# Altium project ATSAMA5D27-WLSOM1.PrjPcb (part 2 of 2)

## Sheet 04 - WiFi-BLE-Flash.SchDoc
size B; CompanyName: Microchip Technology Inc.; Organization: Microchip Technology; Address1: 2355 West Chandler Blvd.; Address2: Chandler, AZ  85224; Address4: USA; SheetNumber: 5; SheetTotal: 6; SheetTitle: WiFi/BLE/FLASH
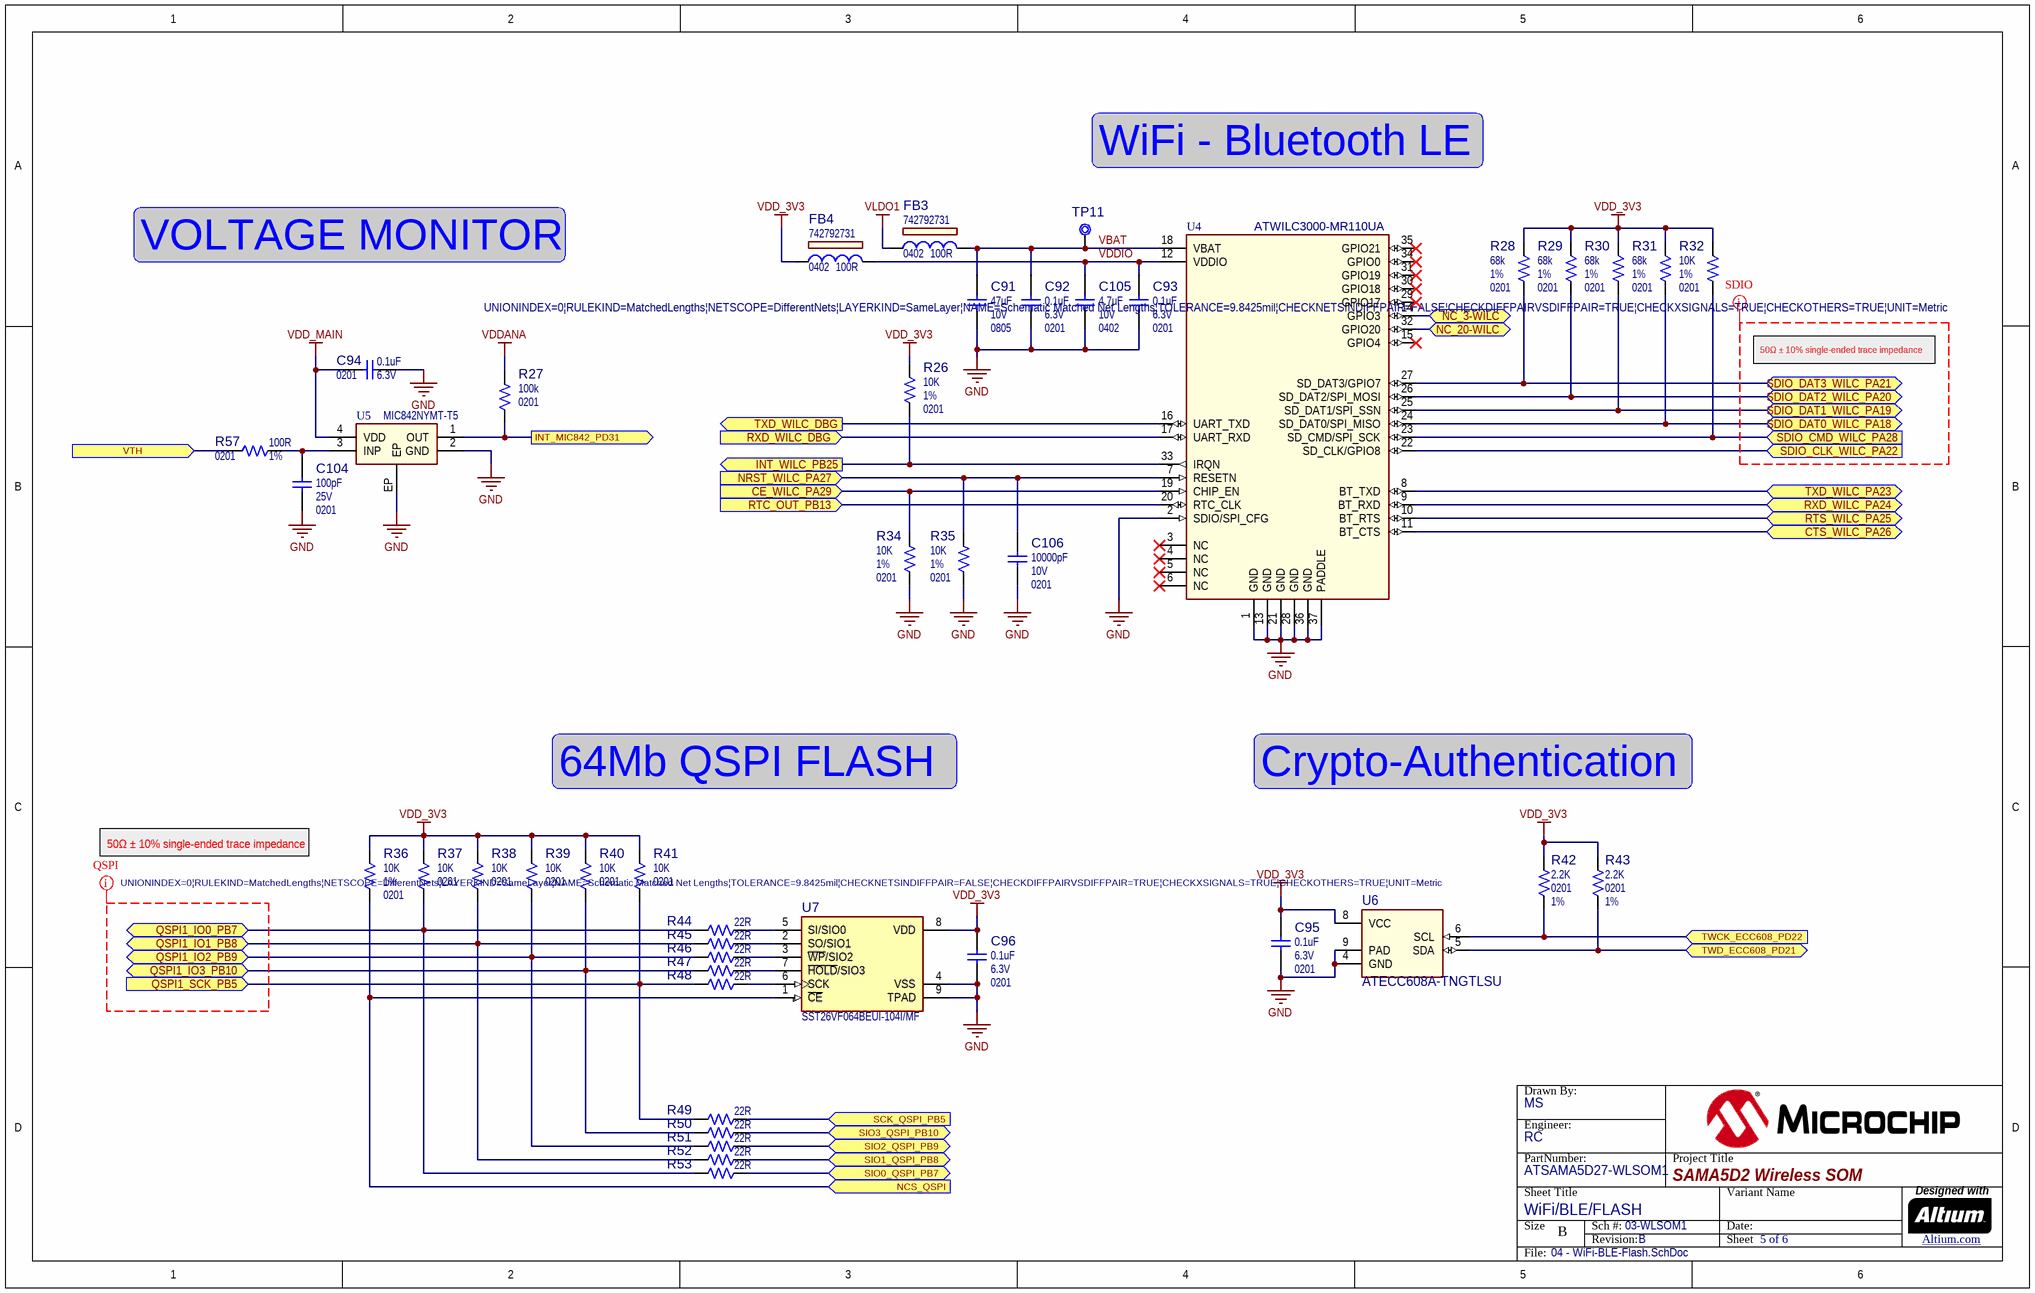
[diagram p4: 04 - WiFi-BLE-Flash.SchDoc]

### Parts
(Parts that share a designator on the sheet are numbered #1, #2 ... from top to bottom, then left to right.)
?#5  (no value)  (graphical)
C91  value 47uF  Voltage: 10V  Package: 0805  [RES_C_0805]  (hidden comment: Capacitor NP)
C92  value 0.1uF  Voltage: 6.3V  Package: 0201  [CAP_C_0201]  (hidden comment: Capacitor NP)
C93  value 0.1uF  Voltage: 6.3V  Package: 0201  [CAP_C_0201]  (hidden comment: Capacitor NP)
C94  value 0.1uF  Voltage: 6.3V  Package: 0201  [CAP_C_0201]  (hidden comment: Capacitor NP)
C95  value 0.1uF  Voltage: 6.3V  Package: 0201  [CAP_C_0201]  (hidden comment: Capacitor NP)
C96  value 0.1uF  Voltage: 6.3V  Package: 0201  [CAP_C_0201]  (hidden comment: Capacitor NP)
C104  value 100pF  Voltage: 25V  Package: 0201  [CAP_C_0201]  (hidden comment: Capacitor NP)
C105  value 4.7uF  Voltage: 10V  Package: 0402  [CAP_C_0402]  (hidden comment: Capacitor NP)
C106  value 10000pF  Voltage: 10V  Package: 0201  [CAP_C_0201]  (hidden comment: Capacitor NP)
FB3  value 100R  Package: 0402  Manufacturer Part Number 1: 742792731  [IND_C_0402]  (hidden comment: Ferrite Bead)
FB4  value 100R  Package: 0402  Manufacturer Part Number 1: 742792731  [IND_C_0402]  (hidden comment: Ferrite Bead)
R26  value 10K  Package: 0201  Tolerance: 1%  [RES_C_0201]  (hidden comment: Resistor)
R27  value 100k  Package: 0201  [RES_C_0201]  (hidden comment: Resistor)
R28  value 68k  Package: 0201  Tolerance: 1%  [RES_C_0201]  (hidden comment: Resistor)
R29  value 68k  Package: 0201  Tolerance: 1%  [RES_C_0201]  (hidden comment: Resistor)
R30  value 68k  Package: 0201  Tolerance: 1%  [RES_C_0201]  (hidden comment: Resistor)
R31  value 68k  Package: 0201  Tolerance: 1%  [RES_C_0201]  (hidden comment: Resistor)
R32  value 10K  Package: 0201  Tolerance: 1%  [RES_C_0201]  (hidden comment: Resistor)
R34  value 10K  Package: 0201  Tolerance: 1%  [RES_C_0201]  (hidden comment: Resistor)
R35  value 10K  Package: 0201  Tolerance: 1%  [RES_C_0201]  (hidden comment: Resistor)
R36  value 10K  Package: 0201  Tolerance: 1%  [RES_C_0201]  (hidden comment: Resistor)
R37  value 10K  Package: 0201  [RES_C_0201]  (hidden comment: Resistor)
R38  value 10K  Package: 0201  [RES_C_0201]  (hidden comment: Resistor)
R39  value 10K  Package: 0201  [RES_C_0201]  (hidden comment: Resistor)
R40  value 10K  Package: 0201  [RES_C_0201]  (hidden comment: Resistor)
R41  value 10K  Package: 0201  [RES_C_0201]  (hidden comment: Resistor)
R42  value 2.2K  Package: 0201  Tolerance: 1%  [RES_C_0201]  (hidden comment: Resistor)
R43  value 2.2K  Package: 0201  Tolerance: 1%  [RES_C_0201]  (hidden comment: Resistor)
R44  value 22R  [RES_C_0201]  (hidden comment: Resistor)
R45  value 22R  [RES_C_0201]  (hidden comment: Resistor)
R46  value 22R  [RES_C_0201]  (hidden comment: Resistor)
R47  value 22R  [RES_C_0201]  (hidden comment: Resistor)
R48  value 22R  [RES_C_0201]  (hidden comment: Resistor)
R49  value 22R  [RES_C_0201]  (hidden comment: Resistor)
R50  value 22R  [RES_C_0201]  (hidden comment: Resistor)
R51  value 22R  [RES_C_0201]  (hidden comment: Resistor)
R52  value 22R  [RES_C_0201]  (hidden comment: Resistor)
R53  value 22R  [RES_C_0201]  (hidden comment: Resistor)
R57  value 100R  Package: 0201  Tolerance: 1%  [RES_C_0201]  (hidden comment: Resistor)
TP11  Test Point No BOM  [TP_1mm_SMD]  (value not drawn)  (no BOM)
U4  value ATWILC3000-MR110UA  [MODULE ATWILC3000-MR110CA]  (hidden comment: MODULE ATWILC3000-MR110CA)
U5  Manufacturer Part Number 1: MIC842NYMT-T5  [TDFN-4_1.6x1.2]  (hidden comment: MIC842 TDFN-4)
U6  value ATECC608A-TNGTLSU  [UDFN-8_2X3_EP1.5X1.3]  (hidden comment: ATECC608A-TNGTLSU UDFN-8)
U7  value SST26VF064BEUI-104I/MF  [WSON-8_6x5_EP3.4X4.0]  (hidden comment: SST26VF064B-104IMF)

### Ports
CE_WILC_PA29 (in), CTS_WILC_PA26 (bidir), INT_MIC842_PD31 (out), INT_WILC_PB25 (out), NC_3-WILC (bidir), NC_20-WILC (bidir), NCS_QSPI (in), NRST_WILC_PA27 (in), QSPI1_IO0_PB7 (bidir), QSPI1_IO1_PB8 (bidir), QSPI1_IO2_PB9 (bidir), QSPI1_IO3_PB10 (bidir), QSPI1_SCK_PB5 (in), RTC_OUT_PB13 (in), RTS_WILC_PA25 (bidir), RXD_WILC_DBG (in), RXD_WILC_PA24 (bidir), SCK_QSPI_PB5 (in), SDIO_CLK_WILC_PA22 (in), SDIO_CMD_WILC_PA28 (in), SDIO_DAT0_WILC_PA18 (bidir), SDIO_DAT1_WILC_PA19 (bidir), SDIO_DAT2_WILC_PA20 (bidir), SDIO_DAT3_WILC_PA21 (bidir), SIO0_QSPI_PB7 (bidir), SIO1_QSPI_PB8 (bidir), SIO2_QSPI_PB9 (bidir), SIO3_QSPI_PB10 (bidir), TWCK_ECC608_PD22 (in), TWD_ECC608_PD21 (bidir), TXD_WILC_DBG (out), TXD_WILC_PA23 (bidir), VTH (in)

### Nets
GND: C91.1 C92.1 C93.1 C94.1 C95.1 C96.1 C104.1 C105.1 C106.1 R34.1 R35.1 U4.1(GND) U4.2(SDIO/SPI_CFG) U4.13(GND) U4.21(GND) U4.28(GND) U4.36(GND) U4.37(PADDLE) U5.2(GND) U5.EP U6.4(GND) U6.9(PAD) U7.4(VSS) U7.9(TPAD)
VDD_3V3: C95.2 C96.2 FB4.1 R26.2 R28.2 R29.2 R30.2 R31.2 R32.2 R36.2 R37.2 R38.2 R39.2 R40.2 R41.2 R42.2 R43.2 U6.8(VCC) U7.8(VDD)
VDD_MAIN: C94.2 U5.4(VDD)
VDDANA: R27.2
VLDO1: FB3.1
CE_WILC_PA29: R34.2 U4.19(CHIP_EN) ; port CE_WILC_PA29
CTS_WILC_PA26: U4.11(BT_CTS) ; port CTS_WILC_PA26
INT_MIC842_PD31: R27.1 U5.1(OUT) ; port INT_MIC842_PD31
INT_WILC_PB25: R26.1 U4.33(IRQN) ; port INT_WILC_PB25
NC_3-WILC: U4.14(GPIO3) ; port NC_3-WILC
NC_20-WILC: U4.32(GPIO20) ; port NC_20-WILC
NCS_QSPI: R36.1 U7.1(~{CE}) ; port NCS_QSPI
NRST_WILC_PA27: C106.2 R35.2 U4.7(RESETN) ; port NRST_WILC_PA27
QSPI1_IO0_PB7: R37.1 R44.1 R53.1 ; port QSPI1_IO0_PB7
QSPI1_IO1_PB8: R38.1 R45.1 R52.1 ; port QSPI1_IO1_PB8
QSPI1_IO2_PB9: R39.1 R46.1 R51.1 ; port QSPI1_IO2_PB9
QSPI1_IO3_PB10: R40.1 R47.1 R50.1 ; port QSPI1_IO3_PB10
QSPI1_SCK_PB5: R41.1 R48.1 R49.1 ; port QSPI1_SCK_PB5
RTC_OUT_PB13: U4.20(RTC_CLK) ; port RTC_OUT_PB13
RTS_WILC_PA25: U4.10(BT_RTS) ; port RTS_WILC_PA25
RXD_WILC_DBG: U4.17(UART_RXD) ; port RXD_WILC_DBG
RXD_WILC_PA24: U4.9(BT_RXD) ; port RXD_WILC_PA24
SCK_QSPI_PB5: R49.2 ; port SCK_QSPI_PB5
SDIO_CLK_WILC_PA22: U4.22(SD_CLK/GPIO8) ; port SDIO_CLK_WILC_PA22
SDIO_CMD_WILC_PA28: R32.1 U4.23(SD_CMD/SPI_SCK) ; port SDIO_CMD_WILC_PA28
SDIO_DAT0_WILC_PA18: R31.1 U4.24(SD_DAT0/SPI_MISO) ; port SDIO_DAT0_WILC_PA18
SDIO_DAT1_WILC_PA19: R30.1 U4.25(SD_DAT1/SPI_SSN) ; port SDIO_DAT1_WILC_PA19
SDIO_DAT2_WILC_PA20: R29.1 U4.26(SD_DAT2/SPI_MOSI) ; port SDIO_DAT2_WILC_PA20
SDIO_DAT3_WILC_PA21: R28.1 U4.27(SD_DAT3/GPIO7) ; port SDIO_DAT3_WILC_PA21
SIO0_QSPI_PB7: R53.2 ; port SIO0_QSPI_PB7
SIO1_QSPI_PB8: R52.2 ; port SIO1_QSPI_PB8
SIO2_QSPI_PB9: R51.2 ; port SIO2_QSPI_PB9
SIO3_QSPI_PB10: R50.2 ; port SIO3_QSPI_PB10
TWCK_ECC608_PD22: R42.1 U6.6(SCL) ; port TWCK_ECC608_PD22
TWD_ECC608_PD21: R43.1 U6.5(SDA) ; port TWD_ECC608_PD21
TXD_WILC_DBG: U4.16(UART_TXD) ; port TXD_WILC_DBG
TXD_WILC_PA23: U4.8(BT_TXD) ; port TXD_WILC_PA23
VBAT: C91.2 C92.2 FB3.2 TP11.1 U4.18(VBAT)
VDDIO: C93.2 C105.2 FB4.2 U4.12(VDDIO)
VTH: R57.1 ; port VTH
NetC104_2: C104.2 R57.2 U5.3(INP)
NetR44_2: R44.2 U7.5(SI/SIO0)
NetR45_2: R45.2 U7.2(SO/SIO1)
NetR46_2: R46.2 U7.3(~{WP}/SIO2)
NetR47_2: R47.2 U7.7(~{HOLD}/SIO3)
NetR48_2: R48.2 U7.6(SCK)

Not connected (* = marked no-connect by the designer): U4 3(NC)* 4(NC)* 5(NC)* 6(NC)* 15(GPIO4)* 29(GPIO17)* 30(GPIO18)* 31(GPIO19)* 34(GPIO0)* 35(GPIO21)*

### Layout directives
net class QSPI; rule Matched Net Lengths [Tolerance = 0.25mm]: (no net found under the mark)
net class SDIO; rule Matched Net Lengths [Tolerance = 0.25mm]: (no net found under the mark)

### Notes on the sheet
- WiFi - Bluetooth LE
- VOLTAGE MONITOR
- 50Ω ± 10% single-ended trace impedance
- 64Mb QSPI FLASH
- Crypto-Authentication

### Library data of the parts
?#5 = Title Block B
C91 = CAP2000: Capacitor; Manufacturer 1: Murata Electronics North America; Manufacturer Part Number 1: GRM21BR61A476ME15L; Description_: CAP CER 47uF 10V 20% X5R 0805; Dev Tools Status: Design; Tolerance: 20%; Temperature Coeffcient: X5R; ESR: 0.3R; Type: Ceramic; Owner: Dragos Danaila; Populated: YES
C92-C96 = CAP2003: Capacitor; Manufacturer 1: KEMET; Manufacturer Part Number 1: C0201C104K9PACTU; Description_: CAP CER 0.1uF 6.3V 10% X5R 0201; Dev Tools Status: Design; Tolerance: 10%; Temperature Coeffcient: X5R; Owner: Dragos Danaila; Populated: YES; ESR: 0.005R; Type: Ceramic
C104 = CAP1450: Capacitor; Manufacturer 1: Murata Electronics North America; Manufacturer Part Number 1: GRM0335C1E101JA01D; Description_: CAP CER 100pF 25V 5% NP0 SMD 0201; Dev Tools Status: Design; Tolerance: 5%; Temperature Coeffcient: NP0; Type: Ceramic; Owner: Gabor Bihari; Populated: YES
C105 = CAP1684: Capacitor; Manufacturer 1: TDK Corporation; Manufacturer Part Number 1: C1005X5R1A475K050BC; Description_: CAP CER 4.7uF 10V 10% X5R SMD 0402; Dev Tools Status: Production; Tolerance: 10%; Temperature Coeffcient: X5R; Type: Ceramic; Owner: Jesus Aviles; Populated: YES
C106 = CAP1201: Capacitor; Manufacturer 1: Murata; Manufacturer Part Number 1: GRM033R61A103KA01D; Description_: CAP CER 10000pF 10V 10% X5R SMD 0201; Dev Tools Status: Production; Tolerance: 10%; Temperature Coeffcient: X5R; Type: Ceramic; Owner: Tad Ahlvers; Populated: YES
FB3 FB4 = IND1642: Manufacturer 1: Wurth Electronics; Description_: FERRITE 100R@100MHz 1.2A SMD 0402; Dev Tools Status: Design; Owner: Dragos Danaila; DCR: 0.09R; RMS Current: 1.2A; Test Frequency: 100MHz; Populated: YES
R26 R32 R34-R36 = RSMT1252: Manufacturer 1: Yageo; Manufacturer Part Number 1: RC0201FR-0710KL; Description_: RES TKF 10K 1% 1/20W SMD 0201; Dev Tools Status: Design; Voltage: 25V; Temperature Coeffcient: 200pm/C; Power: 1/20W; Owner: Dragos Danaila; Populated: YES
R27 = RES1582: Manufacturer 1: Panasonic Electronic Components; Manufacturer Part Number 1: ERJ-1GEF1003C; Tolerance: 1%; Description_: RES TKF 100k 1% 1/20W SMD 0201; Dev Tools Status: Design; Voltage: 15V; Temperature Coeffcient: 200ppm/C; Power: 1/20W; Owner: Gabor Bihari; Populated: YES
R28-R31 = RES2264: Manufacturer 1: Yageo; Manufacturer Part Number 1: RC0201FR-0768KL; Description_: RES TKF 68K 1/20W SMD 0201; Dev Tools Status: Design; Voltage: 25V; Temperature Coeffcient: 200ppm/C; Power: 1/20W; Owner: Dragos Danaila; Populated: YES
R37-R41 = RSMT1252: Manufacturer 1: Yageo; Manufacturer Part Number 1: RC0201FR-0710KL; Tolerance: 1%; Description_: RES TKF 10K 1% 1/20W SMD 0201; Dev Tools Status: Design; Voltage: 25V; Temperature Coeffcient: 200pm/C; Power: 1/20W; Owner: Dragos Danaila; Populated: DNP
R42 R43 = RSMT1251: Manufacturer 1: Vishay Dale; Manufacturer Part Number 1: CRCW02012K20FKED; Description_: RES TKF 2.2K 1/20W SMD 0201; Dev Tools Status: Design; Voltage: 25V; Temperature Coeffcient: 100ppm/C; Current: 0.5A; Power: 1/20W; Owner: Dragos Danaila; Populated: YES
R44-R53 = RES1473: Manufacturer 1: Panasonic Electronic Components; Manufacturer Part Number 1: ERJ-1GEF22R0C; Tolerance: 1%; Description_: RES TKF 22R 1% 1/20W SMD 0201; Dev Tools Status: Design; Voltage: 25V; Power: 1/20W; Owner: Mike Ragsdale; Populated: YES
R57 = RES2175: Manufacturer 1: Yageo; Manufacturer Part Number 1: RC0201FR-07100RL; Description_: RES TKF 100R 1% 1/20W SMD 0201; Dev Tools Status: Design; Voltage: 25V; Temperature Coeffcient: 200ppm/C; Current: 0.5A; Power: 1/20W; Owner: Dragos Danaila; Populated: YES
TP11 = CON1759: Test Point; Value: TP PAD PCB 1mm; Description_: CON TP PAD PCB 1mm SMD; Dev Tools Status: Design; Owner: Cristian Papuc; Populated: YES
U4 = MIC8126: Manufacturer 1: Microchip Technology; Description_: MCHP RF WI-FI 802.11b/g/n ATWILC3000-MR110UA; MAPS Description: SmartConnect WILC3000-MR110UA Module; Dev Tools Status: Design; Owner: Ilie Galan; tblDeviceFamilyID: 11256; FrequencyRange: 2.412-2.472 MHz; MaxSpeedMHz: 0; PowerRX: 84mA (802.11n MCS7); PowerTX: 253mA (802.11n MCS7); Sleep: 1.25uA; Populated: YES
U5 = MIC8024: Manufacturer 1: Microchip Technology; Description_: MCHP ANALOG COMPARATOR 1-CH MIC842NYMT-T5 4-TDFN; MAPS Description: 1.5uA Undervoltage Comparator w/ 1.25% 1.24V Reference, 20mV Hysteresis, Active-; Dev Tools Status: Design; Owner: Dragos Danaila; MPC: 27809THGAE06; LeadContent: Pb-FREE; PackingMedia: T/R; Stage: REL; LeadCount: 4; PackageWidth: 1.2x1.6x0.6mm; ForceMinOrderQtyMult: True; MinOrderQty: 500; TempRange: -40C to +85C; tblDeviceFamilyID: 10172; VDDmax: 0; Channels: 1; TypicalPropDelay: 12000; RailIn: False; Populated: YES
U6 = MIC8843: Manufacturer 1: Microchip Technology Inc; Manufacturer Part Number 1: ATECC608A-TNGTLSU-C; Description_: MCHP INTERFACE CRYPTOAUTH I2C ATECC608A-TNGTLS UDFN8; Dev Tools Status: Design; Owner: Dragos Danaila; Populated: YES
U7 = MIC8649: SQI Serial Flash; Manufacturer 1: Microchip Technology; Description_: MCHP SERIAL FLASH SST26VF064BEUI-104I/MF WDFN-8; MAPS Description: 64Mb 2.3V to 3.6V SQI Flash Memory with EUI48 & EUI64 Mac Addresses; Dev Tools Status: Design; Owner: Dragos Danaila; MPC: S01027U3XEUI; PackingMedia: TUBE; TempRange: -40C to +85C; Stage: REL; LeadCount: 8; PackageWidth: 6x5x0.8mm; ForceMinOrderQtyMult: False; MinOrderQty: 0; LeadContent: Pb-FREE; Busmodes: SPI,SDI,SQI; MemorySize: 64Mb; OpVoltMin: 2,3; OpVoltMax: 3,6; MaxClockFreq: 104 MHz; PageSize_B: 256; WPScheme: Full Array; Endurance: 100,000; Populated: YES

## Sheet 05 - SOM-PIO.SchDoc
size B; CompanyName: Microchip Technology Inc.; Organization: Microchip Technology; Address1: 2355 West Chandler Blvd.; Address2: Chandler, AZ  85224; Address4: USA; SheetNumber: 6; SheetTotal: 6; SheetTitle: SOM PIO
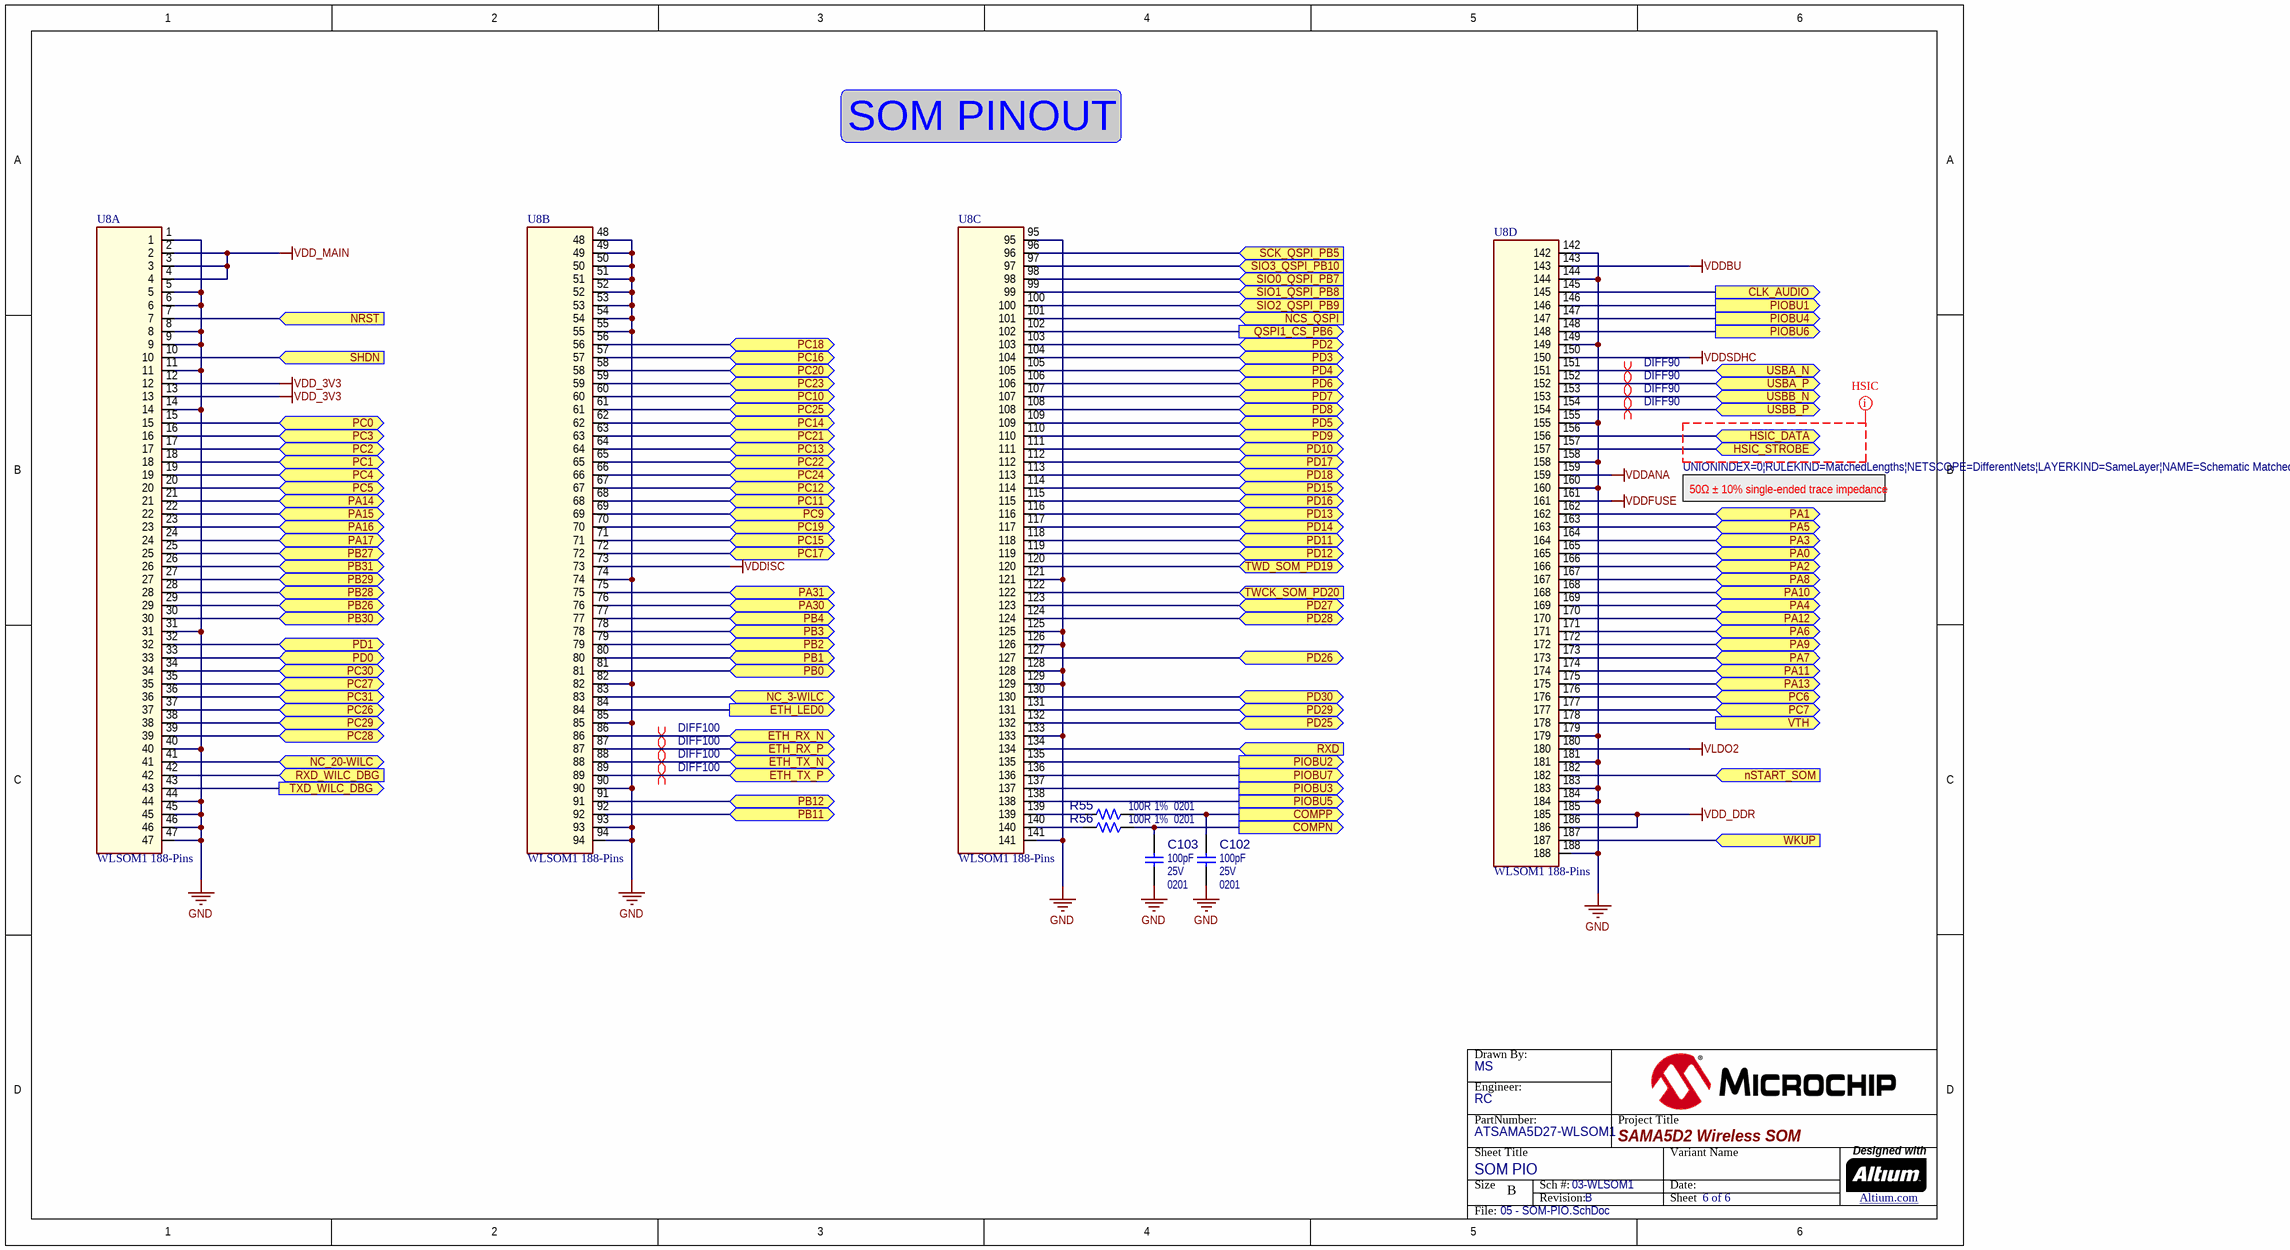
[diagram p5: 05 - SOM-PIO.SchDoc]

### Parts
(Parts that share a designator on the sheet are numbered #1, #2 ... from top to bottom, then left to right.)
?#6  (no value)  (graphical)
C102  value 100pF  Voltage: 25V  Package: 0201  [CAP_C_0201]  (hidden comment: Capacitor NP)
C103  value 100pF  Voltage: 25V  Package: 0201  [CAP_C_0201]  (hidden comment: Capacitor NP)
R55  value 100R  Package: 0201  Tolerance: 1%  [RES_C_0201]  (hidden comment: Resistor)
R56  value 100R  Package: 0201  Tolerance: 1%  [RES_C_0201]  (hidden comment: Resistor)
U8  WLSOM1 188-Pins  [SOM-40.8MMX40.8MM]  (parts A,B,C,D of 4)  (no BOM)

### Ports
CLK_AUDIO (out), COMPN (out), COMPP (out), ETH_LED0 (out), ETH_RX_N (bidir), ETH_RX_P (bidir), ETH_TX_N (bidir), ETH_TX_P (bidir), HSIC_DATA (bidir), HSIC_STROBE (bidir), NC_3-WILC (bidir), NC_20-WILC (bidir), NCS_QSPI (in), NRST (in), nSTART_SOM (in), PA0 (bidir), PA1 (bidir), PA2 (bidir), PA3 (bidir), PA4 (bidir), PA5 (bidir), PA6 (bidir), PA7 (bidir), PA8 (bidir), PA9 (bidir), PA10 (bidir), PA11 (bidir), PA12 (bidir), PA13 (bidir), PA14 (bidir), PA15 (bidir), PA16 (bidir), PA17 (bidir), PA30 (bidir), PA31 (bidir), PB0 (bidir), PB1 (bidir), PB2 (bidir), PB3 (bidir), PB4 (bidir), PB11 (bidir), PB12 (bidir), PB26 (bidir), PB27 (bidir), PB28 (bidir), PB29 (bidir), PB30 (bidir), PB31 (bidir), PC0 (bidir), PC1 (bidir), PC2 (bidir), PC3 (bidir), PC4 (bidir), PC5 (bidir), PC6 (bidir), PC7 (bidir), PC9 (bidir), PC10 (bidir), PC11 (bidir), PC12 (bidir), PC13 (bidir), PC14 (bidir), PC15 (bidir), PC16 (bidir), PC17 (bidir), PC18 (bidir), PC19 (bidir), PC20 (bidir), PC21 (bidir), PC22 (bidir), PC23 (bidir), PC24 (bidir), PC25 (bidir), PC26 (bidir), PC27 (bidir), PC28 (bidir), PC29 (bidir), PC30 (bidir), PC31 (bidir), PD0 (bidir), PD1 (bidir), PD2 (bidir), PD3 (bidir), PD4 (bidir), PD5 (bidir), PD6 (bidir), PD7 (bidir), PD8 (bidir), PD9 (bidir), PD10 (bidir), PD11 (bidir), PD12 (bidir), PD13 (bidir), PD14 (bidir), PD15 (bidir), PD16 (bidir), PD17 (bidir), PD18 (bidir), PD25 (bidir), PD26 (bidir), PD27 (bidir), PD28 (bidir), PD29 (bidir), PD30 (bidir), PIOBU1 (out), PIOBU2 (out), PIOBU3 (out), PIOBU4 (out), PIOBU5 (out), PIOBU6 (out), PIOBU7 (out), QSPI1_CS_PB6 (out), RXD (in), RXD_WILC_DBG (in), SCK_QSPI_PB5 (in), SHDN (in), SIO0_QSPI_PB7 (in), SIO1_QSPI_PB8 (in), SIO2_QSPI_PB9 (in), SIO3_QSPI_PB10 (in), TWCK_SOM_PD20 (in), TWD_SOM_PD19 (bidir), TXD_WILC_DBG (out), USBA_N (bidir), USBA_P (bidir), USBB_N (bidir), USBB_P (bidir), VTH (out), WKUP (in)

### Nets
GND: C102.1 C103.1 U8.1 U8.5 U8.6 U8.8 U8.9 U8.11 U8.14 U8.31 U8.40 U8.44 U8.45 U8.46 U8.47 U8.48 U8.49 U8.50 U8.51 U8.52 U8.53 U8.54 U8.55 U8.74 U8.82 U8.85 U8.90 U8.93 U8.94 U8.95 U8.121 U8.125 U8.126 U8.128 U8.129 U8.133 U8.141 U8.142 U8.144 U8.149 U8.155 U8.158 U8.160 U8.179 U8.181 U8.183 U8.184 U8.188
VDD_3V3: U8.12 U8.13
VDD_DDR: U8.185 U8.186
VDD_MAIN: U8.2 U8.3 U8.4
VDDANA: U8.159
VDDBU: U8.143
VDDFUSE: U8.161
VDDISC: U8.73
VDDSDHC: U8.150
VLDO2: U8.180
CLK_AUDIO: U8.145 ; port CLK_AUDIO
COMPN: C103.2 R56.2 ; port COMPN
COMPP: C102.2 R55.2 ; port COMPP
ETH_LED0: U8.84 ; port ETH_LED0
ETH_RX_N: U8.86 ; port ETH_RX_N
ETH_RX_P: U8.87 ; port ETH_RX_P
ETH_TX_N: U8.88 ; port ETH_TX_N
ETH_TX_P: U8.89 ; port ETH_TX_P
HSIC_DATA: U8.156 ; port HSIC_DATA
HSIC_STROBE: U8.157 ; port HSIC_STROBE
NC_3-WILC: U8.83 ; port NC_3-WILC
NC_20-WILC: U8.41 ; port NC_20-WILC
NCS_QSPI: U8.101 ; port NCS_QSPI
NRST: U8.7 ; port NRST
nSTART_SOM: U8.182 ; port nSTART_SOM
PA0: U8.165 ; port PA0
PA1: U8.162 ; port PA1
PA2: U8.166 ; port PA2
PA3: U8.164 ; port PA3
PA4: U8.169 ; port PA4
PA5: U8.163 ; port PA5
PA6: U8.171 ; port PA6
PA7: U8.173 ; port PA7
PA8: U8.167 ; port PA8
PA9: U8.172 ; port PA9
PA10: U8.168 ; port PA10
PA11: U8.174 ; port PA11
PA12: U8.170 ; port PA12
PA13: U8.175 ; port PA13
PA14: U8.21 ; port PA14
PA15: U8.22 ; port PA15
PA16: U8.23 ; port PA16
PA17: U8.24 ; port PA17
PA30: U8.76 ; port PA30
PA31: U8.75 ; port PA31
PB0: U8.81 ; port PB0
PB1: U8.80 ; port PB1
PB2: U8.79 ; port PB2
PB3: U8.78 ; port PB3
PB4: U8.77 ; port PB4
PB11: U8.92 ; port PB11
PB12: U8.91 ; port PB12
PB26: U8.29 ; port PB26
PB27: U8.25 ; port PB27
PB28: U8.28 ; port PB28
PB29: U8.27 ; port PB29
PB30: U8.30 ; port PB30
PB31: U8.26 ; port PB31
PC0: U8.15 ; port PC0
PC1: U8.18 ; port PC1
PC2: U8.17 ; port PC2
PC3: U8.16 ; port PC3
PC4: U8.19 ; port PC4
PC5: U8.20 ; port PC5
PC6: U8.176 ; port PC6
PC7: U8.177 ; port PC7
PC9: U8.69 ; port PC9
PC10: U8.60 ; port PC10
PC11: U8.68 ; port PC11
PC12: U8.67 ; port PC12
PC13: U8.64 ; port PC13
PC14: U8.62 ; port PC14
PC15: U8.71 ; port PC15
PC16: U8.57 ; port PC16
PC17: U8.72 ; port PC17
PC18: U8.56 ; port PC18
PC19: U8.70 ; port PC19
PC20: U8.58 ; port PC20
PC21: U8.63 ; port PC21
PC22: U8.65 ; port PC22
PC23: U8.59 ; port PC23
PC24: U8.66 ; port PC24
PC25: U8.61 ; port PC25
PC26: U8.37 ; port PC26
PC27: U8.35 ; port PC27
PC28: U8.39 ; port PC28
PC29: U8.38 ; port PC29
PC30: U8.34 ; port PC30
PC31: U8.36 ; port PC31
PD0: U8.33 ; port PD0
PD1: U8.32 ; port PD1
PD2: U8.103 ; port PD2
PD3: U8.104 ; port PD3
PD4: U8.105 ; port PD4
PD5: U8.109 ; port PD5
PD6: U8.106 ; port PD6
PD7: U8.107 ; port PD7
PD8: U8.108 ; port PD8
PD9: U8.110 ; port PD9
PD10: U8.111 ; port PD10
PD11: U8.118 ; port PD11
PD12: U8.119 ; port PD12
PD13: U8.116 ; port PD13
PD14: U8.117 ; port PD14
PD15: U8.114 ; port PD15
PD16: U8.115 ; port PD16
PD17: U8.112 ; port PD17
PD18: U8.113 ; port PD18
PD25: U8.132 ; port PD25
PD26: U8.127 ; port PD26
PD27: U8.123 ; port PD27
PD28: U8.124 ; port PD28
PD29: U8.131 ; port PD29
PD30: U8.130 ; port PD30
PIOBU1: U8.146 ; port PIOBU1
PIOBU2: U8.135 ; port PIOBU2
PIOBU3: U8.137 ; port PIOBU3
PIOBU4: U8.147 ; port PIOBU4
PIOBU5: U8.138 ; port PIOBU5
PIOBU6: U8.148 ; port PIOBU6
PIOBU7: U8.136 ; port PIOBU7
QSPI1_CS_PB6: U8.102 ; port QSPI1_CS_PB6
RXD: U8.134 ; port RXD
RXD_WILC_DBG: U8.42 ; port RXD_WILC_DBG
SCK_QSPI_PB5: U8.96 ; port SCK_QSPI_PB5
SHDN: U8.10 ; port SHDN
SIO0_QSPI_PB7: U8.98 ; port SIO0_QSPI_PB7
SIO1_QSPI_PB8: U8.99 ; port SIO1_QSPI_PB8
SIO2_QSPI_PB9: U8.100 ; port SIO2_QSPI_PB9
SIO3_QSPI_PB10: U8.97 ; port SIO3_QSPI_PB10
TWCK_SOM_PD20: U8.122 ; port TWCK_SOM_PD20
TWD_SOM_PD19: U8.120 ; port TWD_SOM_PD19
TXD_WILC_DBG: U8.43 ; port TXD_WILC_DBG
USBA_N: U8.151 ; port USBA_N
USBA_P: U8.152 ; port USBA_P
USBB_N: U8.153 ; port USBB_N
USBB_P: U8.154 ; port USBB_P
VTH: U8.178 ; port VTH
WKUP: U8.187 ; port WKUP
NetR55_1: R55.1 U8.139
NetR56_1: R56.1 U8.140

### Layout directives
differential pair; differential pair class DIFF90; net class DIFF90: USBA_N, USBA_P, USBB_N, USBB_P
differential pair; differential pair class DIFF100; net class DIFF100: ETH_RX_N, ETH_RX_P, ETH_TX_N, ETH_TX_P
rule Matched Net Lengths [Tolerance = 0.05mm]; net class HSIC: (no net found under the mark)

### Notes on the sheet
- SOM PINOUT
- 50Ω ± 10% single-ended trace impedance

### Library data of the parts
?#6 = Title Block B
C102 C103 = CAP1450: as C104 on sheet 04 - WiFi-BLE-Flash
R55 R56 = RES2175: as R57 on sheet 04 - WiFi-BLE-Flash
U8 = WLSOM-188: 188-Castellated thru-holes, 40.80mm x 40.80mm package

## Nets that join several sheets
DDR_VREF: 01 - Power (C11.1 C16.2 R9.1 R10.2), 02 - MPU (C61.1 C62.1 U2.J10 U2.M12)
GND: 01 - Power (28 pins), 02 - MPU (132 pins), 03 - Ethernet (12 pins), 04 - WiFi-BLE-Flash (24 pins), 05 - SOM-PIO (48 pins)
VDD_3V3: 01 - Power (7 pins), 02 - MPU (14 pins), 03 - Ethernet (9 pins), 04 - WiFi-BLE-Flash (19 pins), 05 - SOM-PIO (U8.12 U8.13)
VDD_DDR: 01 - Power (C9.1 L6.2 U1.32), 02 - MPU (10 pins), 05 - SOM-PIO (U8.185 U8.186)
VDD_MAIN: 01 - Power (14 pins), 04 - WiFi-BLE-Flash (C94.2 U5.4), 05 - SOM-PIO (U8.2 U8.3 U8.4)
VDDANA: 02 - MPU (6 pins), 04 - WiFi-BLE-Flash (R27.2), 05 - SOM-PIO (U8.159)
VDDBU: 02 - MPU (C66.1 U2.V3), 05 - SOM-PIO (U8.143)
VDDCORE: 01 - Power (5 pins), 02 - MPU (20 pins)
VDDFUSE: 02 - MPU (C40.1 U2.U15), 05 - SOM-PIO (U8.161)
VDDIODDR: 01 - Power (7 pins), 02 - MPU (61 pins)
VDDISC: 02 - MPU (C69.1 C99.2 U2.G3), 05 - SOM-PIO (U8.73)
VDDOSC_PLL: 01 - Power (C3.2 L2.2 TP3.1), 02 - MPU (C72.1 C79.1 U2.R6 U2.R10)
VDDPLLA: 01 - Power (C98.2 L5.2 TP8.1), 02 - MPU (C81.1 U2.P9)
VDDSDHC: 02 - MPU (C83.1 C100.1 C107.1 U2.T7), 05 - SOM-PIO (U8.150)
VDDUTMII: 01 - Power (C97.2 FB1.2 TP1.1), 02 - MPU (C75.1 U2.R8)
VLDO1: 01 - Power (C14.2 TP9.1 U1.19), 04 - WiFi-BLE-Flash (FB3.1)
VLDO2: 01 - Power (C15.2 U1.21), 05 - SOM-PIO (U8.180)
CE_WILC_PA29: 02 - MPU (U2.U16), 04 - WiFi-BLE-Flash (R34.2 U4.19)
CLK_AUDIO: 02 - MPU (U2.W2), 05 - SOM-PIO (U8.145)
COMPN: 02 - MPU (U2.V2), 05 - SOM-PIO (C103.2 R56.2)
COMPP: 02 - MPU (U2.V1), 05 - SOM-PIO (C102.2 R55.2)
CTS_WILC_PA26: 02 - MPU (U2.U14), 04 - WiFi-BLE-Flash (U4.11)
ETH_GMDC_PB22: 02 - MPU (U2.E4), 03 - Ethernet (U3.11)
ETH_GMDIO_PB23: 02 - MPU (U2.H2), 03 - Ethernet (R21.1 U3.10)
ETH_GRX0_PB18: 02 - MPU (U2.D3), 03 - Ethernet (U3.13)
ETH_GRX1_PB19: 02 - MPU (U2.F4), 03 - Ethernet (U3.12)
ETH_GRXDV_PB16: 02 - MPU (U2.A4), 03 - Ethernet (R23.2 U3.15)
ETH_GRXER_PB17: 02 - MPU (U2.B3), 03 - Ethernet (U3.17)
ETH_GTX0_PB20: 02 - MPU (U2.F2), 03 - Ethernet (U3.20)
ETH_GTX1_PB21: 02 - MPU (U2.F3), 03 - Ethernet (U3.21)
ETH_GTXCK_PB14: 02 - MPU (U2.G4), 03 - Ethernet (U3.16)
ETH_GTXEN_PB15: 02 - MPU (U2.H4), 03 - Ethernet (U3.19)
ETH_INT_PB24: 02 - MPU (U2.A3), 03 - Ethernet (R20.1 U3.18)
ETH_LED0: 03 - Ethernet (R24.1 U3.23), 05 - SOM-PIO (U8.84)
ETH_RX_N: 03 - Ethernet (U3.3), 05 - SOM-PIO (U8.86)
ETH_RX_P: 03 - Ethernet (U3.4), 05 - SOM-PIO (U8.87)
ETH_TX_N: 03 - Ethernet (U3.5), 05 - SOM-PIO (U8.88)
ETH_TX_P: 03 - Ethernet (U3.6), 05 - SOM-PIO (U8.89)
HSIC_DATA: 02 - MPU (U2.W9), 05 - SOM-PIO (U8.156)
HSIC_STROBE: 02 - MPU (U2.W10), 05 - SOM-PIO (U8.157)
INT_MCP16502_PC8: 01 - Power (R6.1 U1.1), 02 - MPU (U2.P11)
INT_MIC842_PD31: 02 - MPU (U2.P7), 04 - WiFi-BLE-Flash (R27.1 U5.1)
INT_WILC_PB25: 02 - MPU (U2.H1), 04 - WiFi-BLE-Flash (R26.1 U4.33)
NC_3-WILC: 04 - WiFi-BLE-Flash (U4.14), 05 - SOM-PIO (U8.83)
NC_20-WILC: 04 - WiFi-BLE-Flash (U4.32), 05 - SOM-PIO (U8.41)
NCS_QSPI: 04 - WiFi-BLE-Flash (R36.1 U7.1), 05 - SOM-PIO (U8.101)
NRST: 01 - Power (U1.2), 02 - MPU (U2.W3), 03 - Ethernet (R25.1), 05 - SOM-PIO (U8.7)
NRST_WILC_PA27: 02 - MPU (U2.M18), 04 - WiFi-BLE-Flash (C106.2 R35.2 U4.7)
nSTART_SOM: 01 - Power (U1.24), 05 - SOM-PIO (U8.182)
PA0: 02 - MPU (R59.2), 05 - SOM-PIO (U8.165)
PA1: 02 - MPU (U2.R9), 05 - SOM-PIO (U8.162)
PA2: 02 - MPU (U2.W12), 05 - SOM-PIO (U8.166)
PA3: 02 - MPU (U2.V11), 05 - SOM-PIO (U8.164)
PA4: 02 - MPU (U2.W14), 05 - SOM-PIO (U8.169)
PA5: 02 - MPU (U2.V10), 05 - SOM-PIO (U8.163)
PA6: 02 - MPU (U2.W15), 05 - SOM-PIO (U8.171)
PA7: 02 - MPU (U2.W16), 05 - SOM-PIO (U8.173)
PA8: 02 - MPU (U2.V12), 05 - SOM-PIO (U8.167)
PA9: 02 - MPU (U2.V16), 05 - SOM-PIO (U8.172)
PA10: 02 - MPU (U2.V14), 05 - SOM-PIO (U8.168)
PA11: 02 - MPU (U2.L18), 05 - SOM-PIO (U8.174)
PA12: 02 - MPU (U2.T16), 05 - SOM-PIO (U8.170)
PA13: 02 - MPU (U2.K18), 05 - SOM-PIO (U8.175)
PA14: 02 - MPU (U2.R19), 05 - SOM-PIO (U8.21)
PA15: 02 - MPU (U2.L17), 05 - SOM-PIO (U8.22)
PA16: 02 - MPU (U2.N19), 05 - SOM-PIO (U8.23)
PA17: 02 - MPU (U2.M16), 05 - SOM-PIO (U8.24)
PA30: 02 - MPU (U2.U12), 05 - SOM-PIO (U8.76)
PA31: 02 - MPU (U2.U17), 05 - SOM-PIO (U8.75)
PB0: 02 - MPU (U2.C7), 05 - SOM-PIO (U8.81)
PB1: 02 - MPU (U2.A9), 05 - SOM-PIO (U8.80)
PB2: 02 - MPU (U2.A10), 05 - SOM-PIO (U8.79)
PB3: 02 - MPU (U2.A11), 05 - SOM-PIO (U8.78)
PB4: 02 - MPU (U2.A12), 05 - SOM-PIO (U8.77)
PB11: 02 - MPU (U2.B5), 05 - SOM-PIO (U8.92)
PB12: 02 - MPU (U2.A6), 05 - SOM-PIO (U8.91)
PB26: 02 - MPU (U2.G2), 05 - SOM-PIO (U8.29)
PB27: 02 - MPU (U2.H5), 05 - SOM-PIO (U8.25)
PB28: 02 - MPU (U2.J2), 05 - SOM-PIO (U8.28)
PB29: 02 - MPU (U2.J3), 05 - SOM-PIO (U8.27)
PB30: 02 - MPU (U2.A2), 05 - SOM-PIO (U8.30)
PB31: 02 - MPU (U2.J4), 05 - SOM-PIO (U8.26)
PC0: 02 - MPU (U2.T14), 05 - SOM-PIO (U8.15)
PC1: 02 - MPU (U2.R16), 05 - SOM-PIO (U8.18)
PC2: 02 - MPU (U2.T15), 05 - SOM-PIO (U8.17)
PC3: 02 - MPU (U2.T13), 05 - SOM-PIO (U8.16)
PC4: 02 - MPU (U2.P16), 05 - SOM-PIO (U8.19)
PC5: 02 - MPU (U2.L19), 05 - SOM-PIO (U8.20)
PC6: 02 - MPU (U2.R15), 05 - SOM-PIO (U8.176)
PC7: 02 - MPU (U2.N15), 05 - SOM-PIO (U8.177)
PC9: 02 - MPU (U2.B2), 05 - SOM-PIO (U8.69)
PC10: 02 - MPU (U2.K5), 05 - SOM-PIO (U8.60)
PC11: 02 - MPU (U2.C2), 05 - SOM-PIO (U8.68)
PC12: 02 - MPU (U2.D2), 05 - SOM-PIO (U8.67)
PC13: 02 - MPU (U2.K2), 05 - SOM-PIO (U8.64)
PC14: 02 - MPU (U2.K6), 05 - SOM-PIO (U8.62)
PC15: 02 - MPU (U2.B1), 05 - SOM-PIO (U8.71)
PC16: 02 - MPU (U2.K9), 05 - SOM-PIO (U8.57)
PC17: 02 - MPU (U2.C1), 05 - SOM-PIO (U8.72)
PC18: 02 - MPU (U2.L9), 05 - SOM-PIO (U8.56)
PC19: 02 - MPU (U2.D1), 05 - SOM-PIO (U8.70)
PC20: 02 - MPU (U2.L8), 05 - SOM-PIO (U8.58)
PC21: 02 - MPU (U2.E3), 05 - SOM-PIO (U8.63)
PC22: 02 - MPU (U2.E2), 05 - SOM-PIO (U8.65)
PC23: 02 - MPU (U2.L7), 05 - SOM-PIO (U8.59)
PC24: 02 - MPU (U2.E1), 05 - SOM-PIO (U8.66)
PC25: 02 - MPU (U2.L4), 05 - SOM-PIO (U8.61)
PC26: 02 - MPU (U2.D6), 05 - SOM-PIO (U8.37)
PC27: 02 - MPU (U2.E7), 05 - SOM-PIO (U8.35)
PC28: 02 - MPU (U2.J5), 05 - SOM-PIO (U8.39)
PC29: 02 - MPU (U2.C6), 05 - SOM-PIO (U8.38)
PC30: 02 - MPU (U2.D7), 05 - SOM-PIO (U8.34)
PC31: 02 - MPU (U2.C8), 05 - SOM-PIO (U8.36)
PD0: 02 - MPU (U2.J7), 05 - SOM-PIO (U8.33)
PD1: 02 - MPU (U2.D8), 05 - SOM-PIO (U8.32)
PD2: 02 - MPU (U2.J6), 05 - SOM-PIO (U8.103)
PD3: 02 - MPU (U2.M3), 05 - SOM-PIO (U8.104)
PD4: 02 - MPU (U2.L6), 05 - SOM-PIO (U8.105)
PD5: 02 - MPU (U2.L2), 05 - SOM-PIO (U8.109)
PD6: 02 - MPU (U2.J1), 05 - SOM-PIO (U8.106)
PD7: 02 - MPU (U2.L5), 05 - SOM-PIO (U8.107)
PD8: 02 - MPU (U2.K1), 05 - SOM-PIO (U8.108)
PD9: 02 - MPU (U2.L3), 05 - SOM-PIO (U8.110)
PD10: 02 - MPU (U2.L1), 05 - SOM-PIO (U8.111)
PD11: 02 - MPU (U2.N3), 05 - SOM-PIO (U8.118)
PD12: 02 - MPU (U2.M7), 05 - SOM-PIO (U8.119)
PD13: 02 - MPU (U2.N2), 05 - SOM-PIO (U8.116)
PD14: 02 - MPU (U2.M6), 05 - SOM-PIO (U8.117)
PD15: 02 - MPU (U2.M5), 05 - SOM-PIO (U8.114)
PD16: 02 - MPU (U2.M1), 05 - SOM-PIO (U8.115)
PD17: 02 - MPU (U2.M2), 05 - SOM-PIO (U8.112)
PD18: 02 - MPU (U2.M4), 05 - SOM-PIO (U8.113)
PD24: 02 - MPU (U2.N8), 03 - Ethernet (Y3.1)
PD25: 02 - MPU (U2.P8), 05 - SOM-PIO (U8.132)
PD26: 02 - MPU (U2.P2), 05 - SOM-PIO (U8.127)
PD27: 02 - MPU (U2.N5), 05 - SOM-PIO (U8.123)
PD28: 02 - MPU (U2.N4), 05 - SOM-PIO (U8.124)
PD29: 02 - MPU (U2.R2), 05 - SOM-PIO (U8.131)
PD30: 02 - MPU (U2.N10), 05 - SOM-PIO (U8.130)
PIOBU0_PMIC: 01 - Power (Q1.1), 02 - MPU (U2.R4)
PIOBU1: 02 - MPU (U2.R5), 05 - SOM-PIO (U8.146)
PIOBU2: 02 - MPU (U2.R3), 05 - SOM-PIO (U8.135)
PIOBU3: 02 - MPU (U2.T4), 05 - SOM-PIO (U8.137)
PIOBU4: 02 - MPU (U2.U3), 05 - SOM-PIO (U8.147)
PIOBU5: 02 - MPU (U2.T5), 05 - SOM-PIO (U8.138)
PIOBU6: 02 - MPU (U2.U5), 05 - SOM-PIO (U8.148)
PIOBU7: 02 - MPU (U2.P5), 05 - SOM-PIO (U8.136)
QSPI1_CS_PB6: 02 - MPU (U2.B7), 05 - SOM-PIO (U8.102)
QSPI1_IO0_PB7: 02 - MPU (U2.C5), 04 - WiFi-BLE-Flash (R37.1 R44.1 R53.1)
QSPI1_IO1_PB8: 02 - MPU (U2.B8), 04 - WiFi-BLE-Flash (R38.1 R45.1 R52.1)
QSPI1_IO2_PB9: 02 - MPU (U2.B6), 04 - WiFi-BLE-Flash (R39.1 R46.1 R51.1)
QSPI1_IO3_PB10: 02 - MPU (U2.G6), 04 - WiFi-BLE-Flash (R40.1 R47.1 R50.1)
QSPI1_SCK_PB5: 02 - MPU (U2.A7), 04 - WiFi-BLE-Flash (R41.1 R48.1 R49.1)
RTC_OUT_PB13: 02 - MPU (U2.C4), 04 - WiFi-BLE-Flash (U4.20)
RTS_WILC_PA25: 02 - MPU (U2.W18), 04 - WiFi-BLE-Flash (U4.10)
RXD: 02 - MPU (U2.R1), 05 - SOM-PIO (U8.134)
RXD_WILC_DBG: 04 - WiFi-BLE-Flash (U4.17), 05 - SOM-PIO (U8.42)
RXD_WILC_PA24: 02 - MPU (U2.W17), 04 - WiFi-BLE-Flash (U4.9)
SCK_QSPI_PB5: 04 - WiFi-BLE-Flash (R49.2), 05 - SOM-PIO (U8.96)
SDIO_CLK_WILC_PA22: 02 - MPU (U2.V17), 04 - WiFi-BLE-Flash (U4.22)
SDIO_CMD_WILC_PA28: 02 - MPU (U2.U13), 04 - WiFi-BLE-Flash (R32.1 U4.23)
SDIO_DAT0_WILC_PA18: 02 - MPU (U2.V19), 04 - WiFi-BLE-Flash (R31.1 U4.24)
SDIO_DAT1_WILC_PA19: 02 - MPU (U2.V15), 04 - WiFi-BLE-Flash (R30.1 U4.25)
SDIO_DAT2_WILC_PA20: 02 - MPU (U2.T10), 04 - WiFi-BLE-Flash (R29.1 U4.26)
SDIO_DAT3_WILC_PA21: 02 - MPU (U2.U19), 04 - WiFi-BLE-Flash (R28.1 U4.27)
SHDN: 01 - Power (R3.1), 02 - MPU (U2.P4), 05 - SOM-PIO (U8.10)
SIO0_QSPI_PB7: 04 - WiFi-BLE-Flash (R53.2), 05 - SOM-PIO (U8.98)
SIO1_QSPI_PB8: 04 - WiFi-BLE-Flash (R52.2), 05 - SOM-PIO (U8.99)
SIO2_QSPI_PB9: 04 - WiFi-BLE-Flash (R51.2), 05 - SOM-PIO (U8.100)
SIO3_QSPI_PB10: 04 - WiFi-BLE-Flash (R50.2), 05 - SOM-PIO (U8.97)
TWCK_ECC608_PD22: 02 - MPU (U2.N6), 04 - WiFi-BLE-Flash (R42.1 U6.6)
TWCK_MCP16502_PD20: 01 - Power (U1.6), 02 - MPU (R16.2)
TWCK_SOM_PD20: 02 - MPU (R18.2), 05 - SOM-PIO (U8.122)
TWD_ECC608_PD21: 02 - MPU (U2.P3), 04 - WiFi-BLE-Flash (R43.1 U6.5)
TWD_MCP16502_PD19: 01 - Power (U1.5), 02 - MPU (R15.2)
TWD_SOM_PD19: 02 - MPU (R17.2), 05 - SOM-PIO (U8.120)
TXD_WILC_DBG: 04 - WiFi-BLE-Flash (U4.16), 05 - SOM-PIO (U8.43)
TXD_WILC_PA23: 02 - MPU (U2.U18), 04 - WiFi-BLE-Flash (U4.8)
USBA_N: 02 - MPU (U2.V7), 05 - SOM-PIO (U8.151)
USBA_P: 02 - MPU (U2.W7), 05 - SOM-PIO (U8.152)
USBB_N: 02 - MPU (U2.V8), 05 - SOM-PIO (U8.153)
USBB_P: 02 - MPU (U2.W8), 05 - SOM-PIO (U8.154)
VTH: 04 - WiFi-BLE-Flash (R57.1), 05 - SOM-PIO (U8.178)
WKUP: 01 - Power (U1.7), 02 - MPU (U2.U2), 05 - SOM-PIO (U8.187)

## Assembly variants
For-Customer-Reuse: not fitted C17 R37 R38 R39 R40 R41 R58 R60; alternate parts R15 -> RSMT1262, R59 -> RSMT1262, R53 -> RSMT1262, R52 -> RSMT1262, R51 -> RSMT1262, R50 -> RSMT1262, R49 -> RSMT1262, R48 -> RSMT1262, R47 -> RSMT1262, R46 -> RSMT1262, R45 -> RSMT1262, R44 -> RSMT1262, R18 -> RSMT1262, R17 -> RSMT1262, R16 -> RSMT1262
